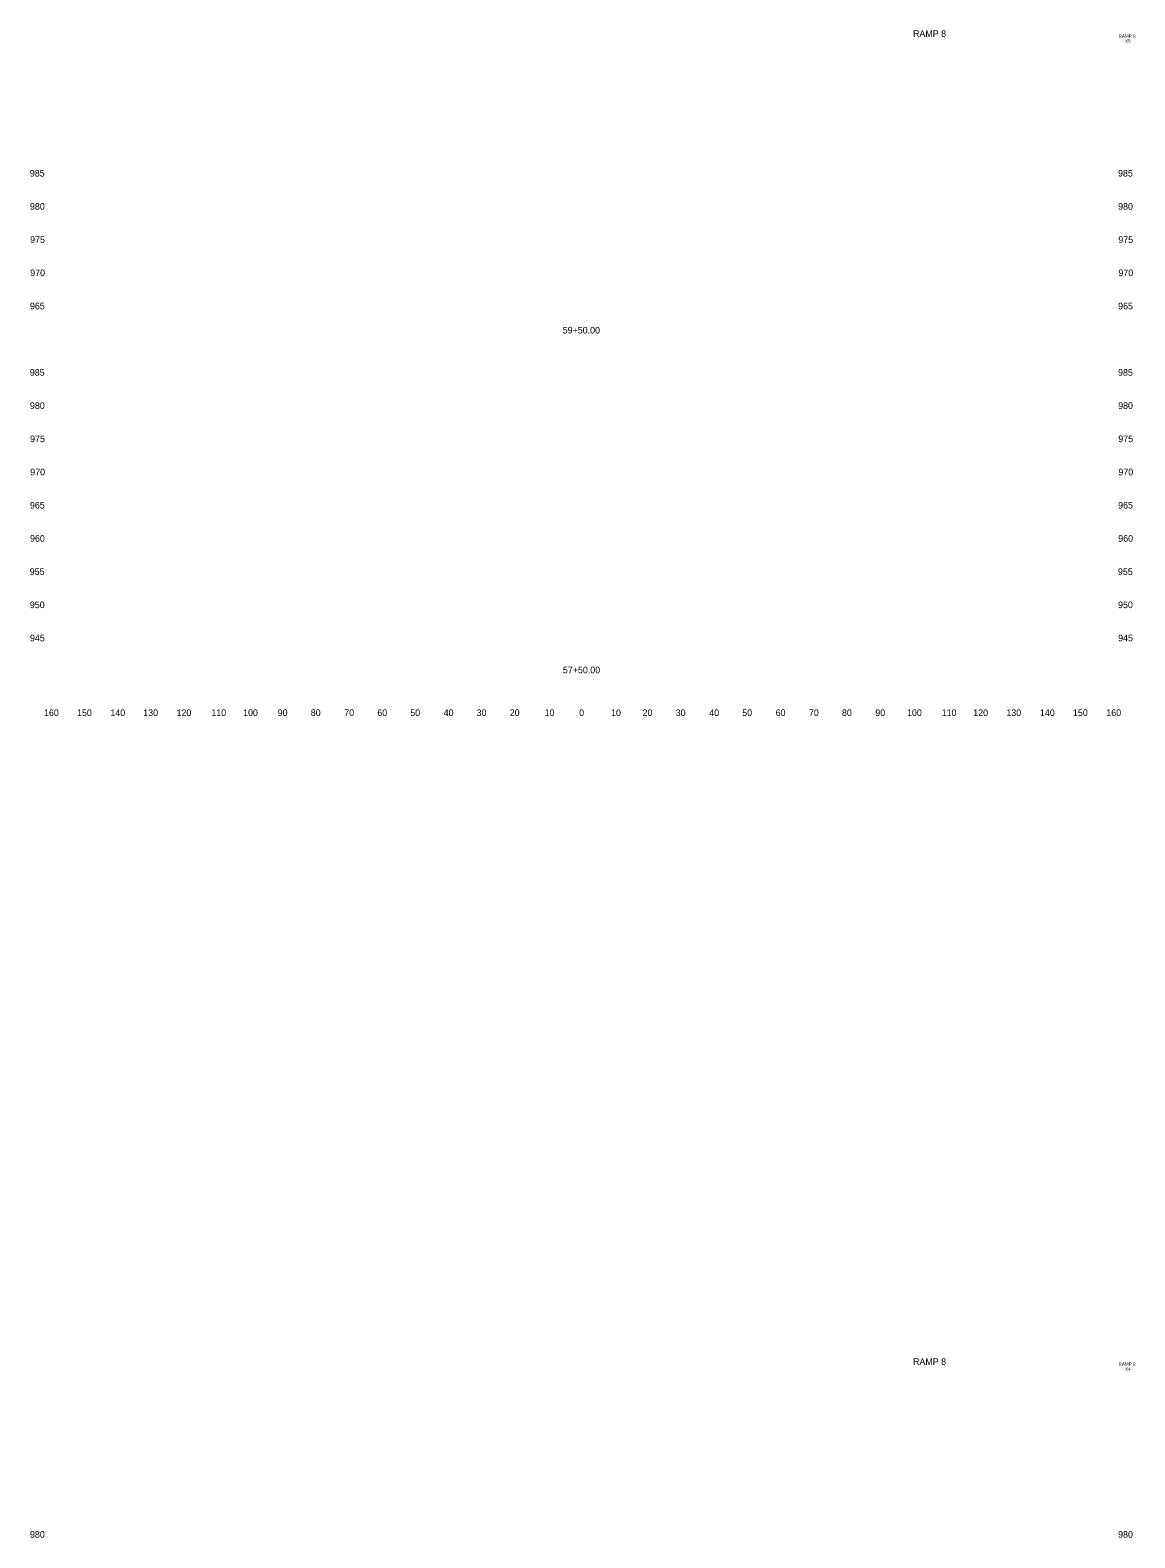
# Model space of a CAD drawing. Extents: x 4994 to 5843, y 4997 to 8804.
# Drawn here: x 4993.9 to 5326.7, y 6350 to 6804.1 of the extents above; entities that cross this region are included whole.
import ezdxf

# ---------------------------------------------------------------- set-up
doc = ezdxf.new("R2010")
doc.units = 0
for name, color, linetype in [('RD_SHT_ID', 7, 'Continuous'), ('RD_XS_TX_Offset', 7, 'Continuous'), ('RD_XS_TX_Station', 7, 'Continuous')]:
    doc.layers.add(name, color=color, linetype=linetype)

msp = doc.modelspace()

# ---------------------------------------------------------------- texts
at = {"layer": 'RD_SHT_ID'}
for s, height, p in [('RAMP 8', 2, (5259.88, 6802.06)), ('RAMP 8', 1, (5321.78, 6801.8)), ('X5', 1, (5323.74, 6800.3)), ('RAMP 8', 2, (5259.88, 6402.06)), ('RAMP 8', 1, (5321.78, 6401.8)), ('X4', 1, (5323.74, 6400.3))]:
    msp.add_text(s, height=height, dxfattribs=at).set_placement(p)
at = {"layer": 'RD_XS_TX_Offset'}
for s, p in [('985', (4993.83, 6760)), ('985', (5321.63, 6760)), ('980', (4993.86, 6750)), ('980', (5321.66, 6750)), ('975', (4993.91, 6740)), ('975', (5321.71, 6740)), ('970', (4993.94, 6730)), ('970', (5321.74, 6730)), ('965', (4993.86, 6720)), ('965', (5321.66, 6720)), ('985', (4993.83, 6700)), ('985', (5321.63, 6700)), ('980', (4993.86, 6690)), ('980', (5321.66, 6690)), ('975', (4993.91, 6680)), ('975', (5321.71, 6680)), ('970', (4993.94, 6670)), ('970', (5321.74, 6670)), ('965', (4993.86, 6660)), ('965', (5321.66, 6660)), ('960', (4993.89, 6650)), ('960', (5321.69, 6650)), ('955', (4993.8, 6640)), ('955', (5321.6, 6640)), ('950', (4993.83, 6630)), ('950', (5321.63, 6630)), ('945', (4993.86, 6620)), ('945', (5321.66, 6620)), ('160', (4998.1, 6597.5)), ('150', (5008.04, 6597.5)), ('140', (5018.1, 6597.5)), ('130', (5027.99, 6597.5)), ('120', (5038.01, 6597.5)), ('110', (5048.51, 6597.5)), ('100', (5058.07, 6597.5)), ('90', (5068.5, 6597.5)), ('80', (5078.46, 6597.5)), ('70', (5088.54, 6597.5)), ('60', (5098.5, 6597.5)), ('50', (5108.43, 6597.5)), ('40', (5118.5, 6597.5)), ('30', (5128.39, 6597.5)), ('20', (5138.4, 6597.5)), ('10', (5148.91, 6597.5)), ('0', (5159.3, 6597.5)), ('0', (5159.3, 6597.5)), ('10', (5168.91, 6597.5)), ('20', (5178.4, 6597.5)), ('30', (5188.39, 6597.5)), ('40', (5198.5, 6597.5)), ('50', (5208.43, 6597.5)), ('60', (5218.5, 6597.5)), ('70', (5228.54, 6597.5)), ('80', (5238.46, 6597.5)), ('90', (5248.5, 6597.5)), ('100', (5258.07, 6597.5)), ('110', (5268.51, 6597.5)), ('120', (5278.01, 6597.5)), ('130', (5287.99, 6597.5)), ('140', (5298.1, 6597.5)), ('150', (5308.04, 6597.5)), ('160', (5318.1, 6597.5)), ('980', (4993.86, 6350)), ('980', (5321.66, 6350))]:
    msp.add_text(s, height=2, dxfattribs=at).set_placement(p)
at = {"layer": 'RD_XS_TX_Station'}
for s, p in [('59+50.00', (5154.35, 6712.72)), ('57+50.00', (5154.4, 6610.38))]:
    msp.add_text(s, height=2, dxfattribs=at).set_placement(p)

doc.saveas('drawing.dxf')
